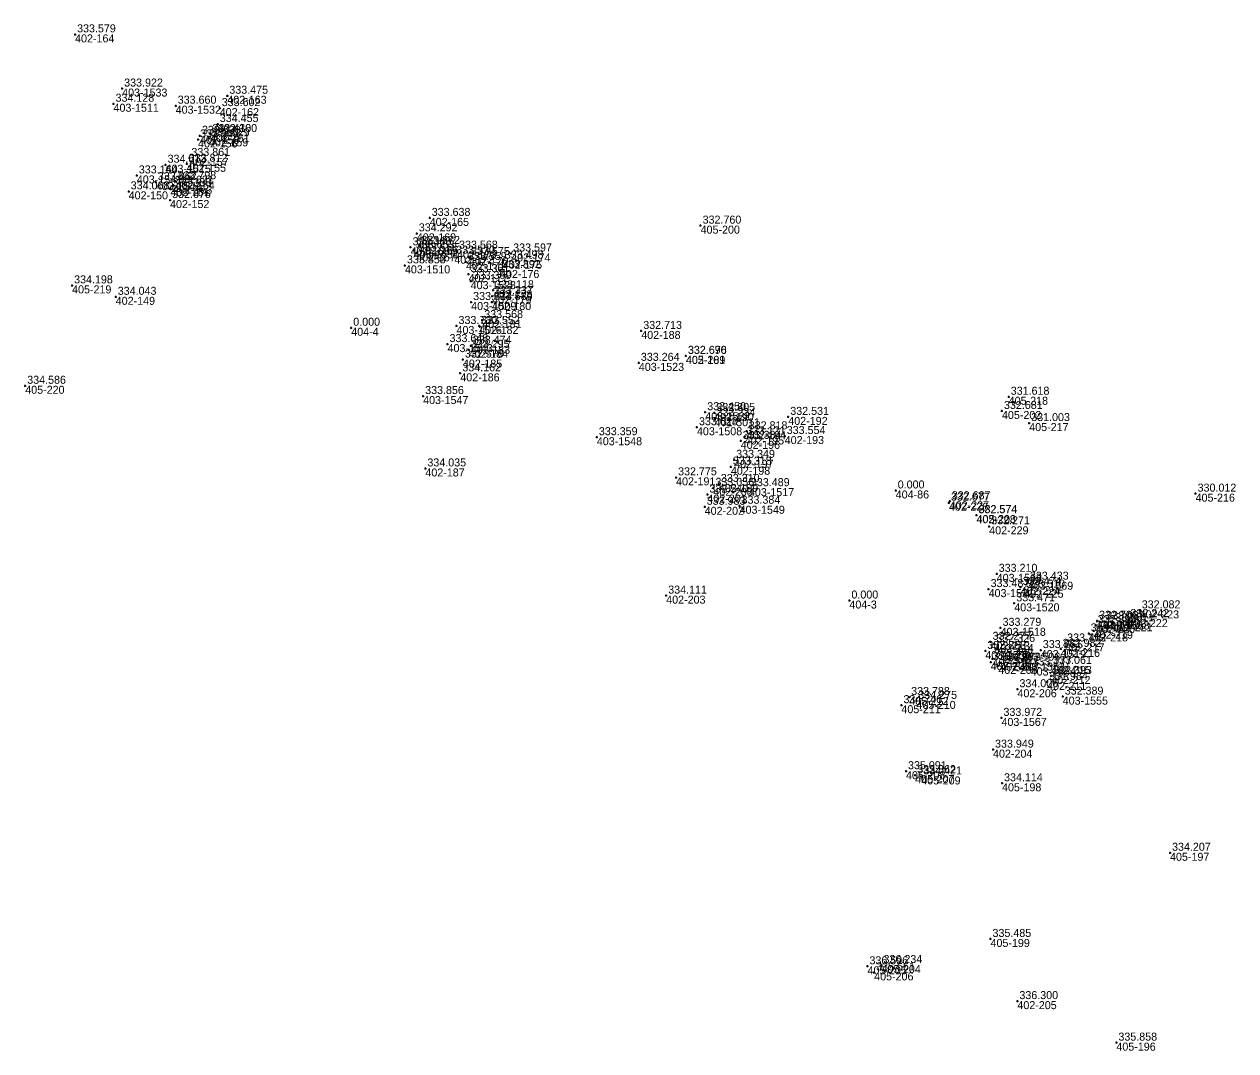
# Model space of a CAD drawing. Extents: x -829398 to -819400, y -1074439 to -1067977.
# Drawn here: x -826672.1 to -826490.5, y -1068948.5 to -1068794.8 of the extents above; entities that cross this region are included whole.
import ezdxf

# ---------------------------------------------------------------- set-up
doc = ezdxf.new("R2010")
doc.units = 0
for name, color, linetype in [('Vrstva 60', 7, 'Continuous'), ('Vrstva 61', 7, 'Continuous'), ('Čísla bodů_doměření_2012', 7, 'Continuous')]:
    doc.layers.add(name, color=color, linetype=linetype)

# ---------------------------------------------------------------- blocks, each defined once
blk = doc.blocks.new('BOD')
at = {"layer": 'Čísla bodů_doměření_2012'}
for p, q in [((-0.15, 0), (0.15, 0)), ((0, -0.15), (0, 0.15))]:
    blk.add_line(p, q, dxfattribs=at)

msp = doc.modelspace()

# ---------------------------------------------------------------- block references
at = {"layer": 'Vrstva 60'}
for p in [(-826664.442, -1068796.268), (-826657.387, -1068804.383), (-826641.623, -1068805.463), (-826658.677, -1068806.657), (-826649.361, -1068806.952), (-826642.761, -1068807.31), (-826643.056, -1068809.699), (-826646.004, -1068812.009), (-826645.721, -1068811.464), (-826644.375, -1068811.844), (-826644.163, -1068811.196), (-826650.878, -1068815.792), (-826647.714, -1068815.651), (-826647.31, -1068814.781), (-826655.19, -1068817.396), (-826656.409, -1068819.782), (-826652.338, -1068818.402), (-826650.155, -1068819.295), (-826649.761, -1068818.935), (-826649.392, -1068818.266), (-826650.205, -1068821.083), (-826611.288, -1068823.762), (-826570.686, -1068824.918), (-826613.227, -1068826.073), (-826614.155, -1068828.162), (-826613.689, -1068828.619), (-826613.289, -1068829.063), (-826612.862, -1068827.962), (-826607.193, -1068828.665), (-826615.001, -1068830.871), (-826607.607, -1068829.412), (-826605.855, -1068830.357), (-826605.39, -1068829.623), (-826600.338, -1068830.168), (-826599.075, -1068829.087), (-826605.455, -1068832.186), (-826600.747, -1068831.566), (-826664.89, -1068833.87), (-826605.146, -1068833.23), (-826658.349, -1068835.58), (-826601.936, -1068835.472), (-826601.783, -1068834.603), (-826605.078, -1068836.364), (-826601.968, -1068836.364), (-826607.271, -1068839.95), (-826603.883, -1068839.946), (-826603.41, -1068839.069), (-826623.05, -1068840.22), (-826579.581, -1068840.694), (-826608.616, -1068842.666), (-826605.428, -1068843.522), (-826605.13, -1068842.908), (-826606.311, -1068844.984), (-826572.891, -1068844.421), (-826572.879, -1068844.439), (-826606.702, -1068847.044), (-826579.945, -1068845.474), (-826671.915, -1068848.91), (-826612.276, -1068850.449), (-826524.505, -1068850.552), (-826525.516, -1068852.683), (-826569.989, -1068852.869), (-826568.625, -1068852.98), (-826568.57, -1068853.763), (-826557.544, -1068853.569), (-826521.433, -1068854.495), (-826571.234, -1068855.122), (-826563.777, -1068855.727), (-826586.238, -1068856.614), (-826564.674, -1068857.158), (-826564.062, -1068856.503), (-826558.079, -1068856.438), (-826611.938, -1068861.293), (-826566.146, -1068861.035), (-826565.649, -1068859.997), (-826574.361, -1068862.626), (-826569.67, -1068865.206), (-826568.761, -1068864.194), (-826567.949, -1068863.618), (-826563.445, -1068864.245), (-826541.44, -1068864.59), (-826496.494, -1068865.067), (-826570.074, -1068867.034), (-826564.844, -1068866.88), (-826533.467, -1068866.422), (-826533.339, -1068866.206), (-826529.344, -1068868.3), (-826529.31, -1068868.275), (-826527.429, -1068869.966), (-826526.306, -1068877.077), (-826527.516, -1068879.367), (-826522.715, -1068879.055), (-826522.18, -1068879.451), (-826521.628, -1068878.258), (-826575.841, -1068880.343), (-826548.38, -1068881.08), (-826523.672, -1068881.498), (-826504.867, -1068882.555), (-826525.725, -1068885.167), (-826511.462, -1068884.765), (-826511.254, -1068884.112), (-826510.174, -1068884.213), (-826508.832, -1068884.481), (-826506.559, -1068883.851), (-826512.512, -1068885.999), (-826511.772, -1068885.596), (-826528.008, -1068888.637), (-826527.228, -1068887.264), (-826526.653, -1068887.591), (-826519.697, -1068888.502), (-826516.714, -1068888.32), (-826516.043, -1068887.514), (-826527.204, -1068890.302), (-826526.934, -1068889.813), (-826525.776, -1068890.402), (-826522.894, -1068890.384), (-826526.063, -1068890.87), (-826521.22, -1068891.12), (-826518.143, -1068892.381), (-826518.14, -1068890.871), (-826523.194, -1068894.365), (-826518.752, -1068893.275), (-826539.431, -1068895.532), (-826538.348, -1068896.107), (-826516.41, -1068895.474), (-826540.587, -1068896.756), (-826525.592, -1068898.662), (-826526.855, -1068903.414), (-826539.899, -1068906.648), (-826538.523, -1068907.239), (-826537.61, -1068907.428), (-826525.505, -1068908.453), (-826500.325, -1068918.866), (-826527.234, -1068931.775), (-826545.675, -1068935.877), (-826543.571, -1068935.684), (-826544.673, -1068936.784), (-826523.205, -1068941.087), (-826508.366, -1068947.307)]:
    msp.add_blockref('BOD', p, dxfattribs=at)

# ---------------------------------------------------------------- texts
for s, p in [('402-164', (-826664.442, -1068797.468)), ('403-1533', (-826657.387, -1068805.583)), ('403-1511', (-826658.677, -1068807.857)), ('403-1532', (-826649.361, -1068808.152)), ('402-163', (-826641.623, -1068806.663)), ('402-162', (-826642.761, -1068808.51)), ('402-160', (-826643.056, -1068810.899)), ('402-156', (-826646.004, -1068813.209)), ('402-158', (-826645.721, -1068812.664)), ('402-159', (-826644.375, -1068813.044)), ('402-161', (-826644.163, -1068812.396)), ('403-1515', (-826650.878, -1068816.992)), ('402-155', (-826647.714, -1068816.851)), ('402-157', (-826647.31, -1068815.981)), ('403-1541', (-826655.19, -1068818.596)), ('402-150', (-826656.409, -1068820.982)), ('403-1542', (-826652.338, -1068819.602)), ('402-151', (-826650.155, -1068820.495)), ('402-153', (-826649.761, -1068820.135)), ('402-154', (-826649.392, -1068819.466)), ('402-152', (-826650.205, -1068822.283)), ('402-165', (-826611.288, -1068824.962)), ('405-200', (-826570.686, -1068826.118)), ('402-169', (-826613.227, -1068827.273)), ('402-168', (-826614.155, -1068829.362)), ('403-1531', (-826613.689, -1068829.819)), ('402-166', (-826612.862, -1068829.162)), ('402-173', (-826607.193, -1068829.865)), ('402-167', (-826613.289, -1068830.263)), ('402-172', (-826607.607, -1068830.612)), ('402-171', (-826605.855, -1068831.557)), ('402-170', (-826605.39, -1068830.823)), ('402-175', (-826600.338, -1068831.368)), ('402-174', (-826599.075, -1068830.287)), ('403-1510', (-826615.001, -1068832.071)), ('402-177', (-826605.455, -1068833.386)), ('402-176', (-826600.747, -1068832.766)), ('405-219', (-826664.89, -1068835.07)), ('403-1528', (-826605.146, -1068834.43)), ('402-149', (-826658.349, -1068836.78)), ('402-179', (-826601.936, -1068836.672)), ('402-178', (-826601.783, -1068835.803)), ('403-1509', (-826605.078, -1068837.564)), ('402-180', (-826601.968, -1068837.564)), ('402-181', (-826603.41, -1068840.269)), ('404-4', (-826623.05, -1068841.42)), ('403-1516', (-826607.271, -1068841.15)), ('402-182', (-826603.883, -1068841.146)), ('402-188', (-826579.581, -1068841.894)), ('403-1543', (-826608.616, -1068843.866)), ('402-183', (-826605.13, -1068844.108)), ('402-185', (-826606.311, -1068846.184)), ('402-184', (-826605.428, -1068844.722)), ('405-201', (-826572.891, -1068845.621)), ('402-189', (-826572.879, -1068845.639)), ('402-186', (-826606.702, -1068848.244)), ('403-1523', (-826579.945, -1068846.674)), ('405-220', (-826671.915, -1068850.11)), ('403-1547', (-826612.276, -1068851.649)), ('405-218', (-826524.505, -1068851.752)), ('403-1522', (-826569.989, -1068854.069)), ('402-190', (-826568.625, -1068854.18)), ('401-5011', (-826568.57, -1068854.963)), ('402-192', (-826557.544, -1068854.769)), ('405-202', (-826525.516, -1068853.883)), ('403-1508', (-826571.234, -1068856.322)), ('402-194', (-826563.777, -1068856.927)), ('405-217', (-826521.433, -1068855.695)), ('403-1548', (-826586.238, -1068857.814)), ('402-196', (-826564.674, -1068858.358)), ('402-195', (-826564.062, -1068857.703)), ('402-193', (-826558.079, -1068857.638)), ('402-187', (-826611.938, -1068862.493)), ('402-198', (-826566.146, -1068862.235)), ('402-197', (-826565.649, -1068861.197)), ('402-191', (-826574.361, -1068863.826)), ('402-201', (-826569.67, -1068866.406)), ('402-200', (-826568.761, -1068865.394)), ('402-199', (-826567.949, -1068864.818)), ('403-1517', (-826563.445, -1068865.445)), ('404-86', (-826541.44, -1068865.79)), ('405-216', (-826496.494, -1068866.267)), ('402-202', (-826570.074, -1068868.234)), ('403-1549', (-826564.844, -1068868.08)), ('402-226', (-826533.467, -1068867.622)), ('402-227', (-826533.339, -1068867.406)), ('402-228', (-826529.344, -1068869.5)), ('405-203', (-826529.31, -1068869.475)), ('402-229', (-826527.429, -1068871.166)), ('403-1568', (-826526.306, -1068878.277)), ('403-1521', (-826527.516, -1068880.567)), ('402-224', (-826522.715, -1068880.255)), ('402-225', (-826522.18, -1068880.651)), ('403-1569', (-826521.628, -1068879.458)), ('402-203', (-826575.841, -1068881.543)), ('404-3', (-826548.38, -1068882.28)), ('403-1520', (-826523.672, -1068882.698)), ('402-223', (-826504.867, -1068883.755)), ('403-1518', (-826525.725, -1068886.367)), ('402-220', (-826511.462, -1068885.965)), ('403-1559', (-826511.254, -1068885.312)), ('403-1558', (-826510.174, -1068885.413)), ('402-221', (-826508.832, -1068885.681)), ('402-222', (-826506.559, -1068885.051)), ('402-218', (-826512.512, -1068887.199)), ('402-219', (-826511.772, -1068886.796)), ('403-1550', (-826528.008, -1068889.837)), ('402-213', (-826527.228, -1068888.464)), ('402-214', (-826526.653, -1068888.791)), ('403-1519', (-826519.697, -1068889.702)), ('402-216', (-826516.714, -1068889.52)), ('402-217', (-826516.043, -1068888.714)), ('402-209', (-826527.204, -1068891.502)), ('402-210', (-826526.934, -1068891.013)), ('402-207', (-826525.776, -1068891.602)), ('403-1553', (-826522.894, -1068891.584)), ('402-208', (-826526.063, -1068892.07)), ('403-1554', (-826521.22, -1068892.32)), ('402-212', (-826518.143, -1068893.581)), ('402-215', (-826518.14, -1068892.071)), ('402-211', (-826518.752, -1068894.475)), ('405-212', (-826539.431, -1068896.732)), ('405-210', (-826538.348, -1068897.307)), ('402-206', (-826523.194, -1068895.565)), ('403-1555', (-826516.41, -1068896.674)), ('405-211', (-826540.587, -1068897.956)), ('403-1567', (-826525.592, -1068899.862)), ('402-204', (-826526.855, -1068904.614)), ('405-208', (-826539.899, -1068907.848)), ('405-207', (-826538.523, -1068908.439)), ('405-209', (-826537.61, -1068908.628)), ('405-198', (-826525.505, -1068909.653)), ('405-197', (-826500.325, -1068920.066)), ('405-199', (-826527.234, -1068932.975)), ('405-205', (-826545.675, -1068937.077)), ('405-204', (-826543.571, -1068936.884)), ('405-206', (-826544.673, -1068937.984)), ('402-205', (-826523.205, -1068942.287)), ('405-196', (-826508.366, -1068948.507))]:
    msp.add_text(s, height=1.2, dxfattribs=at).set_placement(p)
at = {"layer": 'Vrstva 61'}
for s, p in [('333.579', (-826664.142, -1068795.968)), ('333.922', (-826657.087, -1068804.083)), ('334.128', (-826658.377, -1068806.357)), ('333.475', (-826641.323, -1068805.163)), ('333.660', (-826649.061, -1068806.652)), ('333.602', (-826642.461, -1068807.01)), ('334.455', (-826642.756, -1068809.399)), ('333.849', (-826645.704, -1068811.709)), ('333.630', (-826645.421, -1068811.164)), ('333.629', (-826644.075, -1068811.544)), ('333.430', (-826643.863, -1068810.896)), ('334.013', (-826650.578, -1068815.492)), ('333.812', (-826647.414, -1068815.351)), ('333.861', (-826647.01, -1068814.481)), ('333.164', (-826654.89, -1068817.096)), ('333.862', (-826652.038, -1068818.102)), ('333.388', (-826649.855, -1068818.995)), ('333.621', (-826649.461, -1068818.635)), ('333.798', (-826649.092, -1068817.966)), ('334.068', (-826656.109, -1068819.482)), ('332.676', (-826649.905, -1068820.783)), ('333.638', (-826610.988, -1068823.462)), ('332.760', (-826570.386, -1068824.618)), ('334.292', (-826612.927, -1068825.773)), ('333.368', (-826613.855, -1068827.862)), ('333.653', (-826613.389, -1068828.319)), ('333.572', (-826612.562, -1068827.662)), ('333.618', (-826612.989, -1068828.763)), ('333.570', (-826607.307, -1068829.112)), ('333.568', (-826606.893, -1068828.365)), ('333.559', (-826605.555, -1068830.057)), ('333.575', (-826605.09, -1068829.323)), ('333.498', (-826600.038, -1068829.868)), ('333.597', (-826598.775, -1068828.787)), ('333.853', (-826614.701, -1068830.571)), ('333.361', (-826605.155, -1068831.886)), ('333.892', (-826600.447, -1068831.266)), ('334.198', (-826664.59, -1068833.57)), ('333.309', (-826604.846, -1068832.93)), ('334.043', (-826658.049, -1068835.28)), ('333.337', (-826601.636, -1068835.172)), ('333.118', (-826601.483, -1068834.303)), ('333.814', (-826604.778, -1068836.064)), ('333.589', (-826601.668, -1068836.064)), ('333.568', (-826603.11, -1068838.769)), ('0.000', (-826622.75, -1068839.92)), ('333.730', (-826606.971, -1068839.65)), ('333.552', (-826603.583, -1068839.646)), ('332.713', (-826579.281, -1068840.394)), ('333.648', (-826608.316, -1068842.366)), ('333.474', (-826604.83, -1068842.608)), ('333.295', (-826605.128, -1068843.222)), ('332.690', (-826572.591, -1068844.121)), ('332.676', (-826572.579, -1068844.139)), ('332.570', (-826606.011, -1068844.684)), ('333.264', (-826579.645, -1068845.174)), ('334.162', (-826606.402, -1068846.744)), ('334.586', (-826671.615, -1068848.61)), ('333.856', (-826611.976, -1068850.149)), ('331.618', (-826524.205, -1068850.252)), ('333.450', (-826569.689, -1068852.569)), ('332.805', (-826568.325, -1068852.68)), ('333.234', (-826568.27, -1068853.463)), ('332.531', (-826557.244, -1068853.269)), ('332.681', (-826525.216, -1068852.383)), ('333.628', (-826570.934, -1068854.822)), ('332.818', (-826563.477, -1068855.427)), ('331.003', (-826521.133, -1068854.195)), ('333.359', (-826585.938, -1068856.314)), ('333.384', (-826564.374, -1068856.858)), ('333.121', (-826563.762, -1068856.203)), ('333.554', (-826557.779, -1068856.138)), ('334.035', (-826611.638, -1068860.993)), ('333.318', (-826565.846, -1068860.735)), ('333.349', (-826565.349, -1068859.697)), ('332.775', (-826574.061, -1068862.326)), ('333.056', (-826568.461, -1068863.894)), ('333.310', (-826567.649, -1068863.318)), ('333.489', (-826563.145, -1068863.945)), ('0.000', (-826541.14, -1068864.29)), ('332.540', (-826569.37, -1068864.906)), ('332.677', (-826533.167, -1068866.122)), ('332.687', (-826533.039, -1068865.906)), ('330.012', (-826496.194, -1068864.767)), ('333.983', (-826569.774, -1068866.734)), ('333.384', (-826564.544, -1068866.58)), ('332.574', (-826529.044, -1068868)), ('332.574', (-826529.01, -1068867.975)), ('332.271', (-826527.129, -1068869.666)), ('333.210', (-826526.006, -1068876.777)), ('333.487', (-826527.216, -1068879.067)), ('333.474', (-826522.415, -1068878.755)), ('333.510', (-826521.88, -1068879.151)), ('333.433', (-826521.328, -1068877.958)), ('334.111', (-826575.541, -1068880.043)), ('0.000', (-826548.08, -1068880.78)), ('333.471', (-826523.372, -1068881.198)), ('332.082', (-826504.567, -1068882.255)), ('332.398', (-826511.162, -1068884.465)), ('332.706', (-826510.954, -1068883.812)), ('333.037', (-826509.874, -1068883.913)), ('332.911', (-826508.532, -1068884.181)), ('332.242', (-826506.259, -1068883.551)), ('333.279', (-826525.425, -1068884.867)), ('333.169', (-826512.212, -1068885.699)), ('332.861', (-826511.472, -1068885.296)), ('332.277', (-826526.928, -1068886.964)), ('332.326', (-826526.353, -1068887.291)), ('333.261', (-826519.397, -1068888.202)), ('332.982', (-826516.414, -1068888.02)), ('333.113', (-826515.743, -1068887.214)), ('332.863', (-826527.708, -1068888.337)), ('333.430', (-826526.904, -1068890.002)), ('333.422', (-826526.634, -1068889.513)), ('333.427', (-826525.763, -1068890.57)), ('333.379', (-826525.476, -1068890.102)), ('332.506', (-826522.594, -1068890.084)), ('333.177', (-826520.92, -1068890.82)), ('333.061', (-826517.84, -1068890.571)), ('331.984', (-826518.452, -1068892.975)), ('332.393', (-826517.843, -1068892.081)), ('333.788', (-826539.131, -1068895.232)), ('334.006', (-826522.894, -1068894.065)), ('332.389', (-826516.11, -1068895.174)), ('334.746', (-826540.287, -1068896.456)), ('334.275', (-826538.048, -1068895.807)), ('333.972', (-826525.292, -1068898.362)), ('333.949', (-826526.555, -1068903.114)), ('335.091', (-826539.599, -1068906.348)), ('333.862', (-826538.223, -1068906.939)), ('334.421', (-826537.31, -1068907.128)), ('334.114', (-826525.205, -1068908.153)), ('334.207', (-826500.025, -1068918.566)), ('335.485', (-826526.934, -1068931.475)), ('336.234', (-826543.271, -1068935.384)), ('336.596', (-826545.375, -1068935.577)), ('335.661', (-826544.373, -1068936.484)), ('336.300', (-826522.905, -1068940.787)), ('335.858', (-826508.066, -1068947.007))]:
    msp.add_text(s, height=1.2, dxfattribs=at).set_placement(p)

doc.saveas('drawing.dxf')
